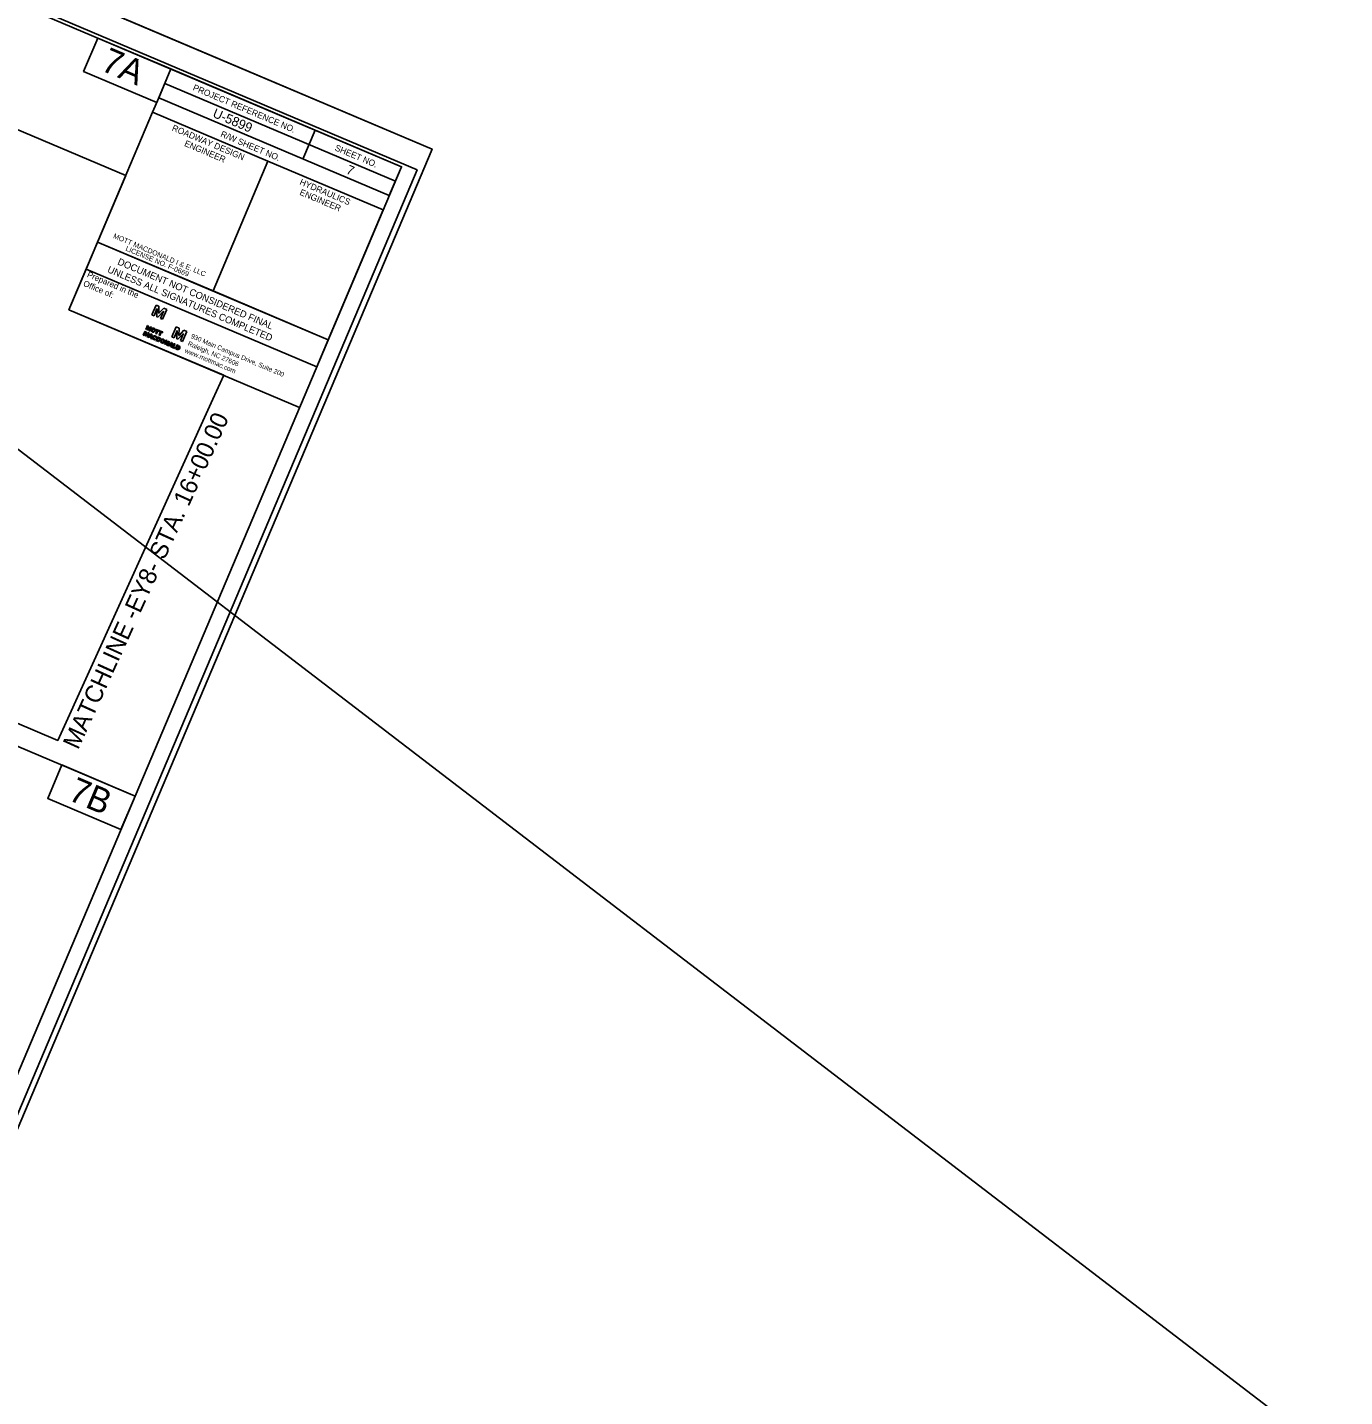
# Model space of a CAD drawing. Extents: x 1616919 to 1619754, y 897646 to 900286.
# Drawn here: x 1618573 to 1619625, y 898633 to 899726 of the extents above; entities that cross this region are included whole.
import ezdxf

# ---------------------------------------------------------------- set-up
doc = ezdxf.new("R2010")
doc.units = 0
for name, color, linetype in [('Exist DTM Breakline Underwater Cogo Elevation', 7, 'Continuous'), ('Exist DTM Breakline Underwater Cogo Number', 7, 'Continuous'), ('Exist DTM Crownline Cogo Elevation', 7, 'Continuous'), ('Exist DTM Crownline Cogo Number', 7, 'Continuous'), ('Exist DTM Crownline Cogo Point CELL', 7, 'Continuous'), ('Exist DTM Regular Point CELL', 7, 'Continuous'), ('Exist DTM Regular Point Cogo Elevation', 7, 'Continuous'), ('Exist DTM Regular Point Cogo Number', 7, 'Continuous'), ('Exist Railroads Signal Milepost CELL', 7, 'Continuous'), ('Exist Railroads Signal Milepost Cogo Number', 7, 'Continuous'), ('Exist Roads EOP', 7, 'Continuous'), ('Exist Roads EOP Cogo Elevation', 7, 'Continuous'), ('Exist Roads EOP Cogo Number', 7, 'Continuous'), ('Exist Roads EOT Cogo Number', 7, 'Continuous')]:
    doc.layers.add(name, color=color, linetype=linetype)

msp = doc.modelspace()

# ---------------------------------------------------------------- linework, layer by layer
at = {"layer": 'Exist DTM Breakline Underwater Cogo Number'}
for points in [[(1618687.5, 899692.9), (1618629.1, 899717.6), (1618617.8, 899691), (1618676.2, 899666.2)], [(1618658.9, 899112.3), (1618600.5, 899137.1), (1618589.1, 899110.4), (1618647.6, 899085.7)]]:
    msp.add_lwpolyline(points, close=True, dxfattribs=at)
at = {"layer": 'Exist DTM Crownline Cogo Elevation'}
msp.add_line((1618896.2, 899628.9), (1617346, 900285.5), dxfattribs=at)
at = {"layer": 'Exist DTM Crownline Cogo Number'}
msp.add_lwpolyline([(1618562.8, 899391.2), (1617924.4, 898557.6), (1619115.3, 897645.5), (1619625.1, 898311.3), (1619435.2, 898456.7), (1619563.8, 898624.6)], close=True, dxfattribs=at)
at = {"layer": 'Exist DTM Crownline Cogo Point CELL'}
msp.add_lwpolyline([(1616938.7, 899290.6), (1618472.8, 898640.8), (1618884.2, 899612.3), (1617350.2, 900262.1)], close=True, dxfattribs=at)
at = {"layer": 'Exist DTM Regular Point Cogo Elevation'}
msp.add_lwpolyline([(1618790.3, 899422.5), (1618606.1, 899500.6), (1618619.9, 899533.1)], dxfattribs=at)
at = {"layer": 'Exist DTM Regular Point Cogo Number'}
for p, q in [((1618675.7, 899504.4), (1618672.4, 899496.6)), ((1618678, 899503.4), (1618675.7, 899504.4)), ((1618672.4, 899496.6), (1618674.1, 899495.9)), ((1618674.1, 899495.9), (1618676.4, 899501.5)), ((1618676.5, 899501.5), (1618676.3, 899494.9)), ((1618676.3, 899494.9), (1618677, 899494.6)), ((1618676.4, 899501.5), (1618676.5, 899501.5)), ((1618677, 899494.6), (1618681.6, 899499.4)), ((1618677.8, 899497.7), (1618677.9, 899497.8)), ((1618677.9, 899497.7), (1618677.8, 899497.7)), ((1618677.9, 899497.8), (1618678, 899503.4)), ((1618681.9, 899501.8), (1618677.9, 899497.8)), ((1618677.9, 899497.8), (1618677.9, 899497.7)), ((1618681.6, 899499.3), (1618679.2, 899493.7)), ((1618679.2, 899493.7), (1618680.9, 899493)), ((1618680.9, 899493), (1618684.2, 899500.8)), ((1618681.6, 899499.4), (1618681.6, 899499.3)), ((1618684.2, 899500.8), (1618681.9, 899501.8)), ((1618666.8, 899483.4), (1618665.5, 899480.4)), ((1618666.2, 899480.1), (1618667.1, 899482.3)), ((1618667.7, 899483), (1618666.8, 899483.4)), ((1618667.1, 899482.3), (1618667, 899479.7)), ((1618667.1, 899482.3), (1618667.1, 899482.3)), ((1618668.8, 899488), (1618667.5, 899485)), ((1618667.5, 899485), (1618668.1, 899484.8)), ((1618667.6, 899480.8), (1618667.7, 899483)), ((1618669.2, 899482.4), (1618667.6, 899480.8)), ((1618668.1, 899484.8), (1618669, 899486.9)), ((1618669.7, 899487.6), (1618668.8, 899488)), ((1618668.8, 899479), (1618670.1, 899482)), ((1618669, 899486.9), (1618669.1, 899486.9)), ((1618669.1, 899486.9), (1618669, 899484.4)), ((1618669, 899486.9), (1618669.1, 899486.9)), ((1618669, 899484.4), (1618669.3, 899484.3)), ((1618670.1, 899482), (1618669.2, 899482.4)), ((1618669.3, 899484.3), (1618671, 899486.1)), ((1618669.6, 899485.5), (1618669.7, 899487.6)), ((1618671.1, 899487), (1618669.6, 899485.5)), ((1618671, 899486.1), (1618670.1, 899483.9)), ((1618670.1, 899483.9), (1618670.8, 899483.6)), ((1618670.8, 899483.6), (1618672, 899486.6)), ((1618671, 899486.1), (1618671, 899486.1)), ((1618671, 899486.1), (1618671, 899486.1)), ((1618671, 899486.1), (1618671, 899486.1)), ((1618672, 899486.6), (1618671.1, 899487)), ((1618691.8, 899486.9), (1618688.4, 899479)), ((1618690.1, 899478.3), (1618692.5, 899484)), ((1618694.1, 899485.9), (1618691.8, 899486.9)), ((1618692.5, 899483.9), (1618692.3, 899477.4)), ((1618692.5, 899484), (1618692.5, 899483.9)), ((1618693, 899477.1), (1618697.6, 899481.8)), ((1618693.9, 899480.2), (1618694.1, 899485.9)), ((1618697.9, 899484.3), (1618694, 899480.2)), ((1618697.7, 899481.8), (1618695.3, 899476.1)), ((1618696.9, 899475.4), (1618700.2, 899483.3)), ((1618697.6, 899481.8), (1618697.7, 899481.8)), ((1618700.2, 899483.3), (1618697.9, 899484.3)), ((1618665.5, 899480.4), (1618666.2, 899480.1)), ((1618667, 899479.7), (1618667.3, 899479.6)), ((1618667.3, 899479.6), (1618669.1, 899481.4)), ((1618669.1, 899481.4), (1618668.2, 899479.3)), ((1618668.2, 899479.3), (1618668.8, 899479)), ((1618669.1, 899481.4), (1618669.1, 899481.4)), ((1618675.3, 899477), (1618674.9, 899477.4)), ((1618675.5, 899478.5), (1618676.1, 899478.6)), ((1618676.2, 899477.6), (1618675.6, 899476.1)), ((1618675.6, 899476.1), (1618676.9, 899475.6)), ((1618676.8, 899479.1), (1618676.2, 899477.6)), ((1618676.4, 899476.4), (1618677.2, 899478.3)), ((1618677.2, 899476.1), (1618676.4, 899476.4)), ((1618678.2, 899478.5), (1618676.8, 899479.1)), ((1618677.2, 899478.3), (1618678, 899478)), ((1618688.4, 899479), (1618690.1, 899478.3)), ((1618691.7, 899471), (1618691.1, 899469.6)), ((1618692.3, 899472.6), (1618691.7, 899471)), ((1618691.9, 899469.9), (1618692.7, 899471.7)), ((1618692.3, 899477.4), (1618693, 899477.1)), ((1618692.3, 899472.6), (1618692.3, 899472.6)), ((1618693.7, 899472), (1618692.3, 899472.6)), ((1618692.7, 899471.7), (1618693.5, 899471.4)), ((1618693.4, 899471.4), (1618693.4, 899471.4)), ((1618694, 899480.2), (1618693.9, 899480.1)), ((1618693.9, 899480.1), (1618693.9, 899480.2)), ((1618693.9, 899480.2), (1618693.9, 899480.2)), ((1618695.3, 899476.1), (1618696.9, 899475.4)), ((1618691.1, 899469.6), (1618692.4, 899469)), ((1618692.7, 899469.6), (1618691.9, 899469.9))]:
    msp.add_line(p, q, dxfattribs=at)
for points in [[(1618675.5, 899484.5), (1618676.4, 899484.1), (1618675.4, 899481.7), (1618676, 899481.4), (1618677.1, 899483.9), (1618677.9, 899483.5), (1618678.2, 899484), (1618675.8, 899485), (1618675.5, 899484.5)], [(1618678.3, 899483.3), (1618679.2, 899483), (1618678.1, 899480.5), (1618678.8, 899480.2), (1618679.8, 899482.7), (1618680.7, 899482.3), (1618680.9, 899482.9), (1618678.5, 899483.9), (1618678.3, 899483.3)], [(1618669.2, 899478.8), (1618669.9, 899478.5), (1618670.3, 899479), (1618671.6, 899478.4), (1618671.5, 899477.8), (1618672.2, 899477.5), (1618672.4, 899481), (1618671.6, 899481.4), (1618669.2, 899478.8)], [(1618670.7, 899479.4), (1618671.7, 899480.5), (1618671.6, 899479), (1618670.7, 899479.4)], [(1618683.7, 899475), (1618683.7, 899475), (1618684.4, 899472.4), (1618684.9, 899472.2), (1618686.2, 899475.1), (1618685.6, 899475.4), (1618684.8, 899473.5), (1618684.2, 899476), (1618683.6, 899476.3), (1618682.3, 899473.3), (1618682.9, 899473), (1618683.7, 899475)], [(1618685.3, 899472), (1618686, 899471.7), (1618686.5, 899472.1), (1618687.7, 899471.6), (1618687.7, 899471), (1618688.4, 899470.7), (1618688.5, 899474.2), (1618687.7, 899474.5), (1618685.3, 899472)], [(1618686.9, 899472.6), (1618687.9, 899473.7), (1618687.8, 899472.2), (1618686.9, 899472.6)], [(1618690.7, 899469.7), (1618690.9, 899470.2), (1618689.6, 899470.8), (1618690.7, 899473.3), (1618690, 899473.5), (1618688.8, 899470.5), (1618690.7, 899469.7)]]:
    msp.add_lwpolyline(points, dxfattribs=at)
msp.add_arc((1618693.1, 899470.5), 1.62, 247.0441, 67.0441, dxfattribs=at)
for centre, major_axis, ratio in [((1618673.4, 899484.3), (0.63, 1.5), 0.993118), ((1618673.4, 899484.3), (0.414, 0.974), 0.916103), ((1618680.9, 899475.6), (0.63, 1.5), 0.993118), ((1618680.9, 899475.6), (0.414, 0.974), 0.916103)]:
    msp.add_ellipse(centre, major_axis=major_axis, ratio=ratio, dxfattribs=at)
for centre, major_axis, ratio, start_param, end_param in [((1618674.5, 899478.3), (0.63, 1.5), 0.993118, 5.246647, 10.366427), ((1618674.5, 899478.3), (0.414, 0.974), 0.916103, 5.276876, 10.296021), ((1618677.6, 899477), (-0.63, -1.49), 0.930276, 0, 3.141593), ((1618677.6, 899477.1), (-0.395, -0.933), 0.900832, 0, 3.141593), ((1618693.1, 899470.5), (-0.395, -0.933), 0.900832, 0, 3.141593)]:
    msp.add_ellipse(centre, major_axis=major_axis, ratio=ratio, start_param=start_param, end_param=end_param, dxfattribs=at)
at = {"layer": 'Exist Railroads Signal Milepost CELL'}
msp.add_lwpolyline([(1617892.5, 899456.8), (1618061.5, 899857.8), (1618651.5, 899607.9), (1618606.1, 899500.6), (1618729.7, 899448.3), (1618721, 899429.2), (1618597.1, 899156.7)], close=True, dxfattribs=at)
at = {"layer": 'Exist Railroads Signal Milepost Cogo Number'}
for p, q in [((1618619.9, 899533.1), (1618629, 899554.7)), ((1618629, 899554.7), (1618813.2, 899476.7)), ((1618804.1, 899455), (1618619.9, 899533.1)), ((1618813.2, 899476.7), (1618804.1, 899455))]:
    msp.add_line(p, q, dxfattribs=at)
at = {"layer": 'Exist Roads EOP'}
for p, q in [((1618682.7, 899681.3), (1618866.9, 899603.3)), ((1618677.8, 899669.8), (1618672.9, 899658.3)), ((1618677.8, 899669.8), (1618862, 899591.8)), ((1618802.7, 899644.1), (1618792.9, 899621)), ((1618765, 899619.3), (1618721.2, 899515.7))]:
    msp.add_line(p, q, dxfattribs=at)
for points in [[(1618871.8, 899614.8), (1617490.5, 900199.9), (1617081, 899233), (1618462.2, 898648)], [(1618687.5, 899692.9), (1618871.8, 899614.8), (1618862, 899591.8), (1618677.8, 899669.8)], [(1618672.9, 899658.3), (1618765, 899619.3), (1618721.2, 899515.7), (1618629, 899554.7)], [(1618765, 899619.3), (1618857.1, 899580.3), (1618813.2, 899476.7), (1618721.2, 899515.7)]]:
    msp.add_lwpolyline(points, close=True, dxfattribs=at)
at = {"layer": 'Exist Roads EOP Cogo Elevation'}
msp.add_lwpolyline([(1616918.9, 899277.3), (1618469.1, 898620.7), (1618896.2, 899628.9), (1617346, 900285.5)], close=True, dxfattribs=at)
at = {"layer": 'Exist Roads EOT Cogo Number'}
for p, q in [((1617277.7, 899697.4), (1618658.9, 899112.3)), ((1618721, 899429.2), (1618597.1, 899156.7))]:
    msp.add_line(p, q, dxfattribs=at)

# ---------------------------------------------------------------- texts
at = {"layer": 'Exist DTM Breakline Underwater Cogo Elevation'}
for s, p in [('MOTT MACDONALD I & E, LLC', (1618641.1, 899558.1)), (' LICENSE NO. F-0669', (1618649.5, 899548.7))]:
    msp.add_text(s, height=4.018, rotation=337.0441, dxfattribs=at).set_placement(p)
at = {"layer": 'Exist DTM Breakline Underwater Cogo Number'}
for s, p in [('7A', (1618630.6, 899692.2)), ('7B', (1618604.5, 899109.6))]:
    msp.add_text(s, height=20, rotation=337.0346, dxfattribs=at).set_placement(p)
at = {"layer": 'Exist DTM Regular Point CELL'}
msp.add_text('MATCHLINE -EY8- STA. 16+00.00', height=14, rotation=65.5437, dxfattribs=at).set_placement((1618613.4, 899148.7))
at = {"layer": 'Exist DTM Regular Point Cogo Number'}
for s, height, p in [('Prepared in the ', 4.819, (1618620.1, 899527)), ('Office of:', 4.82, (1618617, 899519.9)), ('Raleigh, NC 27606', 3.75, (1618700.6, 899472.3)), ('930 Main Campus Drive, Suite 200', 3.75, (1618703.1, 899478.2)), ('www.mottmac.com', 3.75, (1618698.2, 899466.7))]:
    msp.add_text(s, height=height, rotation=337.0441, dxfattribs=at).set_placement(p)
at = {"layer": 'Exist Railroads Signal Milepost Cogo Number'}
for s, p in [('DOCUMENT NOT CONSIDERED FINAL', (1618644.4, 899537)), ('UNLESS ALL SIGNATURES COMPLETED', (1618636.3, 899530.8))]:
    msp.add_text(s, height=5.5, rotation=337.0441, dxfattribs=at).set_placement(p)
at = {"layer": 'Exist Roads EOP'}
for s, p in [('PROJECT REFERENCE NO.', (1618704.6, 899676.2)), ('ROADWAY DESIGN', (1618687.9, 899644)), ('ENGINEER', (1618697.8, 899631.6)), ('R/W SHEET NO.', (1618726.7, 899639.1)), ('SHEET NO.', (1618818, 899628.1)), ('HYDRAULICS', (1618789.9, 899600.8)), ('ENGINEER', (1618789.9, 899592.6))]:
    msp.add_text(s, height=5, rotation=337.0441, dxfattribs=at).set_placement(p)
at = {"layer": 'Exist Roads EOP Cogo Number'}
for s, p in [('U-5899', (1618720.3, 899654.8)), ('7', (1618826.9, 899609.7))]:
    msp.add_text(s, height=7.5, rotation=337.0441, dxfattribs=at).set_placement(p)

doc.saveas('drawing.dxf')
